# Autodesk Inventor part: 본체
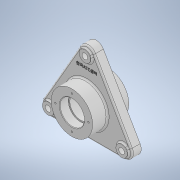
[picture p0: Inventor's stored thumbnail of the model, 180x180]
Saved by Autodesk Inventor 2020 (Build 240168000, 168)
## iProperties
Created: 2023-04
Part Number: 본체
Material: 일반
Document SubType Name: Modeling
Designer: oem
Density: 1 g/cm^3
Appearance: 기본값
Author: oem
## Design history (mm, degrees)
sketch "스케치1" dims "d0" = 164
  geometry: C1 r 16 at (0, 82); C2 r 16 at (-71.014, -41); C3 r 16 at (71.014, -41); 2 further points
  constraints: 3 centre point, 1 coincident, 1 vertical alignment, 9 other
  dimensions: "d1" = 32 diameter of C1; "d6" = 360 deg dimension on point (0, 0) C1.centre (derived)
extrude "돌출1" new body sketch "스케치1" stored distance "d2" = 18; taper "d3" = 0 deg
sketch "스케치2"
  geometry: L1 (0, 114)-(-98.727, -57); L2 (-98.727, -57)-(98.727, -57); L3 (0, 114)-(98.727, -57); C1 r 16 at (0, 82) reference; C2 r 16 at (-71.014, -41) reference; C3 r 16 at (71.014, -41) reference; 7 further points
  constraints: 6 end point, 6 tangent, 1 horizontal
extrude "돌출2" join sketch "스케치2" stored distance "d8" = 18; taper "d9" = 0 deg
sketch "스케치3"
  geometry: C1 r 40 at (0, 0); 1 further point
  constraints: 1 centre point, 1 coincident
  dimensions: "d10" = 80 diameter of C1
extrude "돌출3" join sketch "스케치3" distance "d11" = 29; taper "d12" = 0 deg
sketch "스케치4"
  geometry: C1 r 45 at (0, 0); 1 further point
  constraints: 1 centre point, 1 coincident
  dimensions: "d13" = 90 diameter of C1
extrude "돌출4" join sketch "스케치4" distance "d14" = 5; taper "d15" = 0 deg
sketch "스케치5"
  geometry: C1 r 45 at (0, 0) reference; C2 r 40 at (0, 0)
  constraints: 1 centre point, 1 coincident
  dimensions: "d16" = 80 diameter of C2
extrude "돌출5" join sketch "스케치5" distance "d17" = 18; taper "d18" = 0 deg
sketch "스케치6"
  geometry: L1 (-40, -32)-(40, -32) reference; L2 (0, -32)-(0, 38); L3 (40, 38)-(-40, 38) reference; L4 (0, -32)-(23.5, -32); L5 (23.5, -32)-(23.5, -15); L6 (23.5, -15)-(21, -15); L7 (21, -15)-(21, 21); L8 (21, 21)-(23.5, 21); L9 (23.5, 21)-(23.5, 38); L10 (23.5, 38)-(0, 38); 1 further point
  constraints: 16 end point, 4 perpendicular, 2 midpoint, 2 point on line, 1 collinear, 1 vertical
  dimensions: "d19" = 47 diameter of L9 L2; "d20" = 42 diameter of L7 L2; "d21" = 47 diameter of L5 L2; "d22" = 17 distance between parallel lines of L3 L8; "d23" = 17 distance between parallel lines of L1 L6
revolve "회전1" sketch "스케치6" stored, may be unused: angle "d24" = 90 deg
sketch "스케치7" dims "d25" = 64
  geometry: C1 r 40 at (0, 0) reference; 2 further points
  constraints: 1 coincident, 1 vertical alignment, 2 other
hole "구멍1" sketch "스케치7" at (0, 32) diameter "d26" = 3.242; stored, may be unused: countersink angle "d30" = 90 deg, drill point angle "d32" = 118 deg; dims "d27" = 8, "d28" = 4, "d29" = 2, "d31" = 10
node "작업 평면1"
sketch "스케치8"
  geometry: C1 r 11 at (71.014, -41); A1 r 16 centre (71.014, -41) between (71.014, -57) and (84.87, -33) reference
  constraints: 1 centre point, 1 coincident
  dimensions: "d36" = 22 diameter of C1
extrude "돌출6" join sketch "스케치8" distance "d37" = 4; taper "d38" = 0 deg
sketch "스케치9"
  geometry: C1 r 11 at (0, 0) reference; C2 r 5.5 at (0, 0); 1 further point
  constraints: 1 centre point, 1 coincident
  dimensions: "d39" = 11 diameter of C2
extrude "돌출7" cut sketch "스케치9" extent not by distance; stored distance "d40" = 0; taper "d41" = 0 deg
node "작업 평면2"
sketch "스케치10"
  geometry: 2 further points
  constraints: 1 vertical alignment, 1 other
  dimensions: "d46" = 60 distance of point (0, 0) point (0, 60)
feature "엠보싱1" sketch "스케치10" dims "d2" = 18, "d3" = 0, "d11" = 29, "d12" = 0, "d47" = 0.5, "d48" = 0
fillet "모깎기1" dims "d49" = 0.6
fillet "모깎기2" dims "d50" = 3
chamfer "모따기1" distance "d51" = 1; stored, may be unused: second distance "d52" = 2, angle "d53" = 45 deg
node "솔리드1"
pattern_circular "원형 패턴1" dims angle "d34" = 360 deg
mirror "미러1"
pattern_circular "원형 패턴2" dims angle "d43" = 360 deg
feature "A9D066F2-1C7D-4E18-AEED-F7BC21143FA4" dims "d26" = 3.242, "d27" = 8, "d28" = 4, "d29" = 2, "d30" = 90 deg, "d31" = 10, "d32" = 118 deg
other parameters: "d45" = 45.75
